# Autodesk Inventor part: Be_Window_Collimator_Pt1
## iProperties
Shininess: 64.0
Length Units: 11269
Angle Units: 11279
Time Units: 11290
Mass Units: 11283
Length Display Precision: 3
Angle Display Precision: 2
Compacted: True
Part Number: Be_Window_Collimator_Pt1
Document SubType Name: Modeling
Created: 2004-07
Project: Mucap
Material: Stainless Steel, Austenitic
Description: Mucap, Be Window Collimator
Designer: John Blackburn
Manufacturer: Standard
Standards Organization: Custom
Density: 0.0
Volumn: 0.0
Area: 0.0
PropertySet Name: Model Information
Control State: 0
Master: False
Checked Out: False
Title: Mucap, Be Window Collimator
Subject: Mucap
Author: John Blackburn
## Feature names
1. Revolution1
2. Hole1
3. Circular Pattern1
4. Extrusion1
5. Hole2
6. Circular Pattern2
